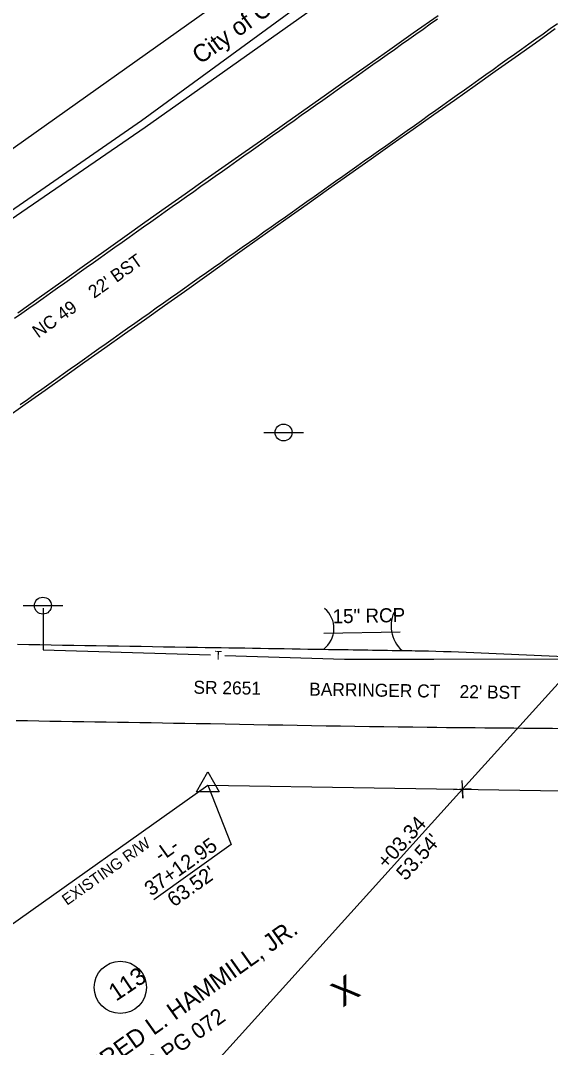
# Model space of a CAD drawing. Extents: x 1577032 to 1581865, y 611492 to 615011.
# Drawn here: x 1580404.9 to 1580555.6, y 613575.1 to 613867.3 of the extents above; entities that cross this region are included whole.
import ezdxf

# ---------------------------------------------------------------- set-up
doc = ezdxf.new("R2010")
doc.units = 0
for name, color, linetype in [('Exist Property Corner CELL', 7, 'Continuous'), ('Exist Property Deed Book Text', 7, 'Continuous'), ('Exist Property Line', 7, 'Continuous'), ('Exist Property Owner Text', 7, 'Continuous'), ('Exist Property Tie Line', 7, 'Continuous'), ('Exist Property Tie Line Text', 7, 'Continuous'), ('Exist Right of Way Line', 7, 'Continuous'), ('Exist Right of Way Line Text', 7, 'Continuous'), ('Exist Right of Way Monument CELL', 7, 'Continuous'), ('Exist Right of Way Monument Leader', 7, 'Continuous'), ('Exist Right of Way Monument Text', 7, 'Continuous'), ('Exist Roads EOP', 7, 'Continuous'), ('Exist Roads EOP Text', 7, 'Continuous'), ('Exist Roads EOT', 7, 'Continuous'), ('Exist Structure Minor Pipes RCP 15 Inch', 7, 'Continuous'), ('Exist Structure Minor Pipes RCP 15 Inch Text', 7, 'Continuous'), ('Exist Utilities Telephone Pole CELL', 7, 'Continuous'), ('Exist Utilities Telephone UG FO SUE LOS B', 7, 'Continuous'), ('Exist Utilities Water UG Line SUE LOS B', 7, 'Continuous'), ('Exist Utilities Water UG Line SUE LOS B Text', 7, 'Continuous'), ('Exist Vegetation Tree CELL', 7, 'Continuous'), ('Old_Level_15', 7, 'Continuous'), ('Old_Level_25', 7, 'Continuous'), ('Scratch_Level_4', 7, 'Continuous')]:
    doc.layers.add(name, color=color, linetype=linetype)

msp = doc.modelspace()

# ---------------------------------------------------------------- linework, layer by layer
at = {"layer": 'Exist Property Corner CELL'}
msp.add_line((1580530.61, 613648.57), (1580530.61, 613648.57), dxfattribs=at)
msp.add_lwpolyline([(1580530.48, 613651.06), (1580530.73, 613646.07), (1580530.61, 613648.57), (1580533.1, 613648.69), (1580528.11, 613648.44)], dxfattribs=at)
at = {"layer": 'Exist Property Line'}
msp.add_line((1580530.61, 613648.57), (1580313.76, 613408.32), dxfattribs=at)
at = {"layer": 'Exist Property Tie Line'}
msp.add_line((1580566.48, 613688.31), (1580530.61, 613648.57), dxfattribs=at)
at = {"layer": 'Exist Right of Way Line'}
msp.add_line((1578304.92, 612120.6), (1580458.22, 613649.74), dxfattribs=at)
for points in [[(1580350.49, 613793.9), (1581560.23, 614652.99)], [(1580458.22, 613649.74), (1580694.67, 613645.91)]]:
    msp.add_lwpolyline(points, dxfattribs=at)
at = {"layer": 'Exist Right of Way Monument CELL'}
msp.add_line((1580458.22, 613649.74), (1580458.22, 613649.74), dxfattribs=at)
msp.add_lwpolyline([(1580454.97, 613647.85), (1580458.22, 613653.49), (1580461.47, 613647.85)], close=True, dxfattribs=at)
at = {"layer": 'Exist Right of Way Monument Leader'}
msp.add_lwpolyline([(1580458.22, 613649.74), (1580464.8, 613632.84), (1580442.81, 613617.08)], dxfattribs=at)
at = {"layer": 'Exist Roads EOP'}
for points in [[(1580523.67, 613868.72), (1580516.6, 613863.71), (1580509.95, 613859), (1580503.52, 613854.45), (1580497.27, 613850.04), (1580491.25, 613845.78), (1580485.5, 613841.72), (1580479.99, 613837.82), (1580474.44, 613833.91), (1580468.79, 613829.96), (1580463.1, 613825.97), (1580457.4, 613821.97), (1580451.71, 613817.95), (1580446.02, 613813.92), (1580440.33, 613809.87), (1580434.56, 613805.75), (1580428.61, 613801.52), (1580422.5, 613797.18), (1580416.38, 613792.81), (1580410.25, 613788.44), (1580404.13, 613784.08)], [(1580400.62, 613754.19), (1580406.26, 613758.19), (1580411.9, 613762.17), (1580417.56, 613766.18), (1580423.23, 613770.21), (1580428.89, 613774.22), (1580434.54, 613778.21), (1580440.2, 613782.2), (1580445.86, 613786.22), (1580451.55, 613790.26), (1580457.23, 613794.32), (1580462.92, 613798.39), (1580468.66, 613802.49), (1580474.49, 613806.64), (1580480.4, 613810.85), (1580486.41, 613815.11), (1580492.51, 613819.43), (1580498.62, 613823.76), (1580504.65, 613828.02), (1580510.61, 613832.22), (1580516.55, 613836.41), (1580522.49, 613840.58), (1580528.38, 613844.72), (1580534.19, 613848.83), (1580539.91, 613852.9), (1580545.63, 613856.96), (1580551.35, 613861.01), (1580557.01, 613865.03)]]:
    msp.add_lwpolyline(points, dxfattribs=at)
for points in [[(1580404.06, 613689.83), (1580455.22, 613689), (1580491.15, 613688.42), (1580513.43, 613688.06)], [(1580513.43, 613688.06), (1580520.92, 613687.94), (1580589.58, 613686.82), (1580621.12, 613689.72), (1580661.54, 613686.76)], [(1580403.71, 613668.15), (1580454.87, 613667.32), (1580520.57, 613666.25), (1580608.23, 613664.83), (1580666.57, 613662.17), (1580712.03, 613659.84), (1580756.49, 613652.31), (1580801.49, 613639.76), (1580839.51, 613619.48), (1580875.28, 613593.59), (1580905.28, 613565.99), (1580935.48, 613537.65)]]:
    msp.add_spline(points, degree=3, dxfattribs=at)
at = {"layer": 'Exist Roads EOT'}
for points in [[(1580523.47, 613867.71), (1580521.43, 613866.27), (1580519.39, 613864.83), (1580517.36, 613863.38), (1580515.32, 613861.94), (1580513.28, 613860.49), (1580511.24, 613859.05), (1580509.21, 613857.6), (1580507.17, 613856.16), (1580505.13, 613854.71), (1580503.1, 613853.27), (1580501.06, 613851.83), (1580499.02, 613850.38), (1580496.98, 613848.94), (1580494.95, 613847.49), (1580492.91, 613846.05), (1580490.87, 613844.6), (1580488.83, 613843.16), (1580486.79, 613841.72), (1580484.76, 613840.28), (1580482.72, 613838.83), (1580480.68, 613837.39), (1580478.64, 613835.95), (1580476.6, 613834.5), (1580474.56, 613833.06), (1580472.52, 613831.62), (1580470.49, 613830.18), (1580468.45, 613828.73), (1580466.41, 613827.29), (1580464.37, 613825.85), (1580462.33, 613824.41), (1580460.29, 613822.96), (1580458.25, 613821.52), (1580456.22, 613820.08), (1580454.18, 613818.64), (1580452.14, 613817.19), (1580450.1, 613815.75), (1580448.06, 613814.31), (1580446.02, 613812.86), (1580443.99, 613811.42), (1580441.95, 613809.97), (1580439.91, 613808.53), (1580437.88, 613807.08), (1580435.84, 613805.64), (1580433.81, 613804.19), (1580431.77, 613802.74), (1580429.73, 613801.3), (1580427.7, 613799.85), (1580425.66, 613798.41), (1580423.63, 613796.96), (1580421.59, 613795.51), (1580419.55, 613794.07), (1580417.52, 613792.62), (1580415.48, 613791.18), (1580413.44, 613789.73), (1580411.41, 613788.28), (1580409.37, 613786.84), (1580407.34, 613785.39), (1580405.3, 613783.94), (1580403.26, 613782.5)], [(1580404.85, 613758.07), (1580406.88, 613759.52), (1580408.92, 613760.97), (1580410.95, 613762.41), (1580412.99, 613763.86), (1580415.02, 613765.31), (1580417.06, 613766.76), (1580419.09, 613768.2), (1580421.13, 613769.65), (1580423.16, 613771.1), (1580425.2, 613772.55), (1580427.24, 613773.99), (1580429.27, 613775.44), (1580431.31, 613776.88), (1580433.35, 613778.33), (1580435.39, 613779.77), (1580437.42, 613781.21), (1580439.46, 613782.65), (1580441.5, 613784.09), (1580443.54, 613785.54), (1580445.58, 613786.98), (1580447.62, 613788.42), (1580449.66, 613789.86), (1580451.7, 613791.31), (1580453.74, 613792.75), (1580455.78, 613794.19), (1580457.82, 613795.63), (1580459.85, 613797.07), (1580461.89, 613798.52), (1580463.93, 613799.96), (1580465.97, 613801.4), (1580468.01, 613802.84), (1580470.05, 613804.28), (1580472.09, 613805.73), (1580474.13, 613807.17), (1580476.17, 613808.61), (1580478.2, 613810.05), (1580480.24, 613811.5), (1580482.28, 613812.94), (1580484.32, 613814.38), (1580486.36, 613815.83), (1580488.4, 613817.27), (1580490.43, 613818.71), (1580492.47, 613820.16), (1580494.51, 613821.6), (1580496.55, 613823.04), (1580498.59, 613824.49), (1580500.62, 613825.93), (1580502.66, 613827.37), (1580504.7, 613828.82), (1580506.74, 613830.26), (1580508.78, 613831.7), (1580510.82, 613833.15), (1580512.85, 613834.59), (1580514.89, 613836.03), (1580516.93, 613837.48), (1580518.97, 613838.92), (1580521, 613840.37), (1580523.03, 613841.82), (1580525.07, 613843.27), (1580527.1, 613844.73), (1580529.13, 613846.18), (1580531.16, 613847.63), (1580533.2, 613849.08), (1580535.23, 613850.53), (1580537.26, 613851.98), (1580539.3, 613853.43), (1580541.33, 613854.88), (1580543.36, 613856.33), (1580545.4, 613857.78), (1580547.43, 613859.23), (1580549.46, 613860.68), (1580551.5, 613862.13), (1580553.53, 613863.58), (1580555.56, 613865.03), (1580557.6, 613866.48)]]:
    msp.add_lwpolyline(points, dxfattribs=at)
at = {"layer": 'Exist Structure Minor Pipes RCP 15 Inch'}
msp.add_line((1580491.17, 613692.98), (1580512.89, 613693.41), dxfattribs=at)
at = {"layer": 'Exist Utilities Telephone Pole CELL'}
for p, q in [((1580474.08, 613750.1), (1580485.42, 613750.1)), ((1580479.75, 613750.1), (1580479.75, 613750.1)), ((1580405.64, 613700.83), (1580416.97, 613700.83)), ((1580411.31, 613700.83), (1580411.31, 613700.83))]:
    msp.add_line(p, q, dxfattribs=at)
for centre in [(1580479.75, 613750.1), (1580411.31, 613700.83)]:
    msp.add_circle(centre, 2.41, dxfattribs=at)
at = {"layer": 'Exist Utilities Telephone UG FO SUE LOS B'}
msp.add_lwpolyline([(1579762.43, 613445.5), (1579805.52, 613477.49), (1579874.3, 613528.42), (1579927.63, 613567.61), (1579961.57, 613589.13), (1580023.79, 613630.1), (1580048.6, 613644.24), (1580064.79, 613652.02), (1580101.01, 613664.86), (1580134.79, 613676.2), (1580157.3, 613683.34), (1580171.65, 613687.07), (1580205.63, 613699.27), (1580257.8, 613718.78), (1580277.93, 613732.3), (1580322.48, 613762.42), (1580357.71, 613789.14), (1580371.84, 613797.02), (1580398.85, 613808.57), (1580440.4, 613836.96), (1580497.32, 613877.42), (1580541.92, 613911.34), (1580565.99, 613928.5)], dxfattribs=at)
at = {"layer": 'Exist Utilities Water UG Line SUE LOS B'}
for p, q in [((1580439.29, 613838.87), (1580495.19, 613879.8)), ((1580397.3, 613809.79), (1580439.29, 613838.87))]:
    msp.add_line(p, q, dxfattribs=at)
at = {"layer": 'Old_Level_15'}
for points in [[(1580411.41, 613700.1), (1580411.33, 613688.27), (1580458.94, 613686.79)], [(1580463.04, 613686.66), (1580497.03, 613685.61), (1580522.49, 613685.63)], [(1580522.49, 613685.63), (1580581.95, 613685.67)]]:
    msp.add_lwpolyline(points, dxfattribs=at)
at = {"layer": 'Old_Level_25'}
msp.add_circle((1580433.31, 613592.2), 7.44, dxfattribs=at)
at = {"layer": 'Scratch_Level_4'}
for centre, radius, start, end in [((1580486.62, 613694.34), 7.45, 307.3777, 49.9394), ((1580519.6, 613695.01), 9.3, 150.0786, 228.3576)]:
    msp.add_arc(centre, radius, start, end, dxfattribs=at)

# ---------------------------------------------------------------- texts
at = {"layer": 'Exist Property Deed Book Text'}
msp.add_text('DB 619 PG 072', height=4.5, rotation=35.38, dxfattribs=at).set_placement((1580429.25, 613558.57))
at = {"layer": 'Exist Property Owner Text'}
msp.add_text('LARRY E. & FRED L. HAMMILL, JR.', height=5, rotation=35.38, dxfattribs=at).set_placement((1580394.9, 613544.38))
at = {"layer": 'Exist Property Tie Line Text'}
for s, p in [('+03.34', (1580508.98, 613625.68)), ("53.54'", (1580514.46, 613622.35))]:
    msp.add_text(s, height=4.2, rotation=47.93, dxfattribs=at).set_placement(p)
at = {"layer": 'Exist Right of Way Line Text'}
msp.add_text('EXISTING R/W', height=3.2, rotation=35.38, dxfattribs=at).set_placement((1580418.15, 613615.4))
at = {"layer": 'Exist Right of Way Monument Text'}
for s, p in [('37+12.95', (1580442.06, 613618)), ('-L-', (1580444.82, 613627.7)), ("63.52'", (1580448.57, 613614.9))]:
    msp.add_text(s, height=4.2, rotation=35.4552, dxfattribs=at).set_placement(p)
at = {"layer": 'Exist Roads EOP Text'}
for s, rotation, p in [("NC 49    22' BST", 35.38, (1580409.96, 613776.83)), ("SR 2651          BARRINGER CT    22' BST", 359.0712, (1580454.08, 613675.78))]:
    msp.add_text(s, height=3.6909, rotation=rotation, dxfattribs=at).set_placement(p)
at = {"layer": 'Exist Structure Minor Pipes RCP 15 Inch Text'}
msp.add_text('15" RCP', height=4, rotation=1.1423, dxfattribs=at).set_placement((1580493.73, 613695.78))
at = {"layer": 'Exist Utilities Water UG Line SUE LOS B Text'}
msp.add_text('City of Concord 30" DIP', height=5, rotation=35.7195, dxfattribs=at).set_placement((1580456.02, 613854.72))
at = {"layer": 'Exist Vegetation Tree CELL'}
msp.add_text('X', height=7.38, rotation=34.1625, dxfattribs=at).set_placement((1580496.58, 613586.42))
at = {"layer": 'Old_Level_15'}
msp.add_text('T', height=2.46, rotation=358.2265, dxfattribs=at).set_placement((1580460.13, 613685.52))
at = {"layer": 'Old_Level_25'}
msp.add_text('113', height=4.921, rotation=33.9997, dxfattribs=at).set_placement((1580432.1, 613588.09))

doc.saveas('drawing.dxf')
